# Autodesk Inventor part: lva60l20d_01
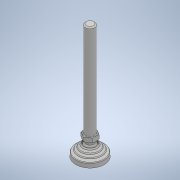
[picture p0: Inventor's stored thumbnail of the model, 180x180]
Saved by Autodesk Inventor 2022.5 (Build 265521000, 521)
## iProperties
Part Number: lva60l20d_01
Material: 一般
Document SubType Name: Modeling
Designer: ImaoCorp
Density: 1 g/cm^3
Appearance: 既定
Author: ImaoCorp
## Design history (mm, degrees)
feature "lva60l20d_01"
node "ソリッド1"
